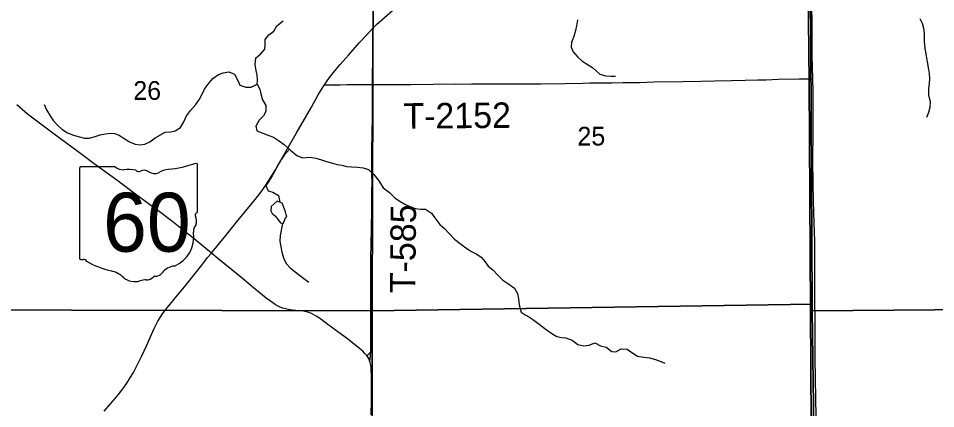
# Model space of a CAD drawing. Extents: x 1874609 to 2204689, y 815661 to 1281160.
# Drawn here: x 2036147 to 2046979, y 997204 to 1001810 of the extents above; entities that cross this region are included whole.
import ezdxf

# ---------------------------------------------------------------- set-up
doc = ezdxf.new("R2010")
doc.units = 0
for name, color, linetype in [('GM_X_County_Road', 7, 'Continuous'), ('GM_X_Minor_Lake', 7, 'Continuous'), ('GM_X_Minor_River', 7, 'Continuous'), ('GM_X_Section', 7, 'Continuous'), ('GM_X_Section_Text', 7, 'Continuous'), ('GM_X_State_Location', 7, 'Continuous'), ('GM_X_State_Route', 7, 'Continuous'), ('GM_X_State_Shield', 7, 'Continuous'), ('GM_X_Township', 7, 'Continuous'), ('GM_X_Township_Road', 7, 'Continuous'), ('GM_X_Township_Road_Text', 7, 'Continuous')]:
    doc.layers.add(name, color=color, linetype=linetype)

msp = doc.modelspace()

# ---------------------------------------------------------------- linework, layer by layer
at = {"layer": 'GM_X_County_Road'}
for points in [[(2040336, 1001697), (2040378, 1001739), (2040439, 1001794), (2040600, 1001935)], [(2039764, 1001027), (2039785, 1001059), (2039823, 1001112), (2039884, 1001190), (2039948, 1001265), (2040045, 1001376), (2040177, 1001523), (2040254, 1001608), (2040332, 1001692), (2040336, 1001697)], [(2038426, 999040), (2038435, 999050), (2038581, 999227), (2038725, 999406), (2038943, 999672), (2039014, 999762), (2039062, 999829), (2039098, 999883), (2039183, 1000023), (2039322, 1000265), (2039429, 1000450), (2039607, 1000763), (2039689, 1000906), (2039739, 1000990), (2039764, 1001027)], [(2037159, 997176), (2037235, 997262), (2037289, 997324), (2037341, 997387), (2037381, 997439), (2037427, 997506), (2037471, 997575), (2037505, 997631), (2037551, 997718), (2037601, 997821), (2037663, 997955), (2037703, 998045), (2037752, 998149), (2037796, 998237), (2037820, 998280), (2037848, 998321), (2037888, 998374), (2037992, 998500), (2038129, 998664), (2038221, 998779), (2038312, 998896), (2038382, 998987), (2038426, 999040)]]:
    msp.add_lwpolyline(points, dxfattribs=at)
at = {"layer": 'GM_X_Minor_Lake'}
for points in [[(2039262, 999630), (2039204, 999654), (2039168, 999622), (2039134, 999591), (2039127, 999539), (2039143, 999507), (2039185, 999475), (2039211, 999435), (2039241, 999396), (2039275, 999388), (2039289, 999424), (2039299, 999446), (2039317, 999470), (2039309, 999496), (2039301, 999528), (2039291, 999560)], [(2039291, 999560), (2039262, 999630)]]:
    msp.add_lwpolyline(points, dxfattribs=at)
at = {"layer": 'GM_X_Minor_River'}
for points in [[(2042751, 1001793), (2042739, 1001723), (2042725, 1001665), (2042706, 1001597), (2042680, 1001525), (2042674, 1001471), (2042697, 1001415), (2042753, 1001353), (2042803, 1001309), (2042875, 1001261), (2042929, 1001229), (2043014, 1001153), (2043086, 1001131), (2043144, 1001126), (2043198, 1001126)], [(2046791, 1001809), (2046819, 1001751), (2046835, 1001695), (2046844, 1001635), (2046842, 1001538), (2046851, 1001454), (2046869, 1001366), (2046881, 1001298), (2046894, 1001208), (2046902, 1001158), (2046908, 1001098), (2046904, 1001046), (2046893, 1000978), (2046893, 1000905), (2046913, 1000829), (2046911, 1000759), (2046896, 1000699), (2046870, 1000641)], [(2037763, 1000399), (2037880, 1000466), (2037948, 1000469), (2038000, 1000481), (2038062, 1000521), (2038100, 1000589), (2038131, 1000658), (2038179, 1000724), (2038243, 1000794), (2038285, 1000855), (2038318, 1000917), (2038344, 1000973), (2038384, 1001031), (2038442, 1001100), (2038509, 1001146), (2038565, 1001166), (2038631, 1001179), (2038700, 1001151), (2038738, 1001075), (2038762, 1001021), (2038832, 1000999), (2038898, 1000997), (2038966, 1001032), (2038972, 1001082), (2038966, 1001142), (2038957, 1001196), (2038945, 1001260), (2038951, 1001344), (2039005, 1001386), (2039056, 1001445), (2039062, 1001497), (2039060, 1001559), (2039104, 1001615), (2039164, 1001660), (2039201, 1001722), (2039275, 1001780)], [(2038966, 1001032), (2039000, 1000974), (2039011, 1000918), (2039031, 1000850), (2039069, 1000782), (2039068, 1000709), (2039042, 1000659), (2038990, 1000607), (2038950, 1000539), (2038962, 1000481), (2039033, 1000453), (2039103, 1000429), (2039159, 1000409), (2039219, 1000369), (2039287, 1000323), (2039362, 1000256), (2039436, 1000192), (2039502, 1000164), (2039590, 1000170), (2039660, 1000161), (2039726, 1000141), (2039786, 1000119), (2039857, 1000101), (2039913, 1000085), (2039965, 1000076), (2040027, 1000062), (2040081, 1000058), (2040153, 1000052), (2040217, 1000044), (2040283, 1000027), (2040343, 999969), (2040402, 999893), (2040454, 999811), (2040528, 999753), (2040591, 999693), (2040643, 999655), (2040709, 999618), (2040769, 999588), (2040835, 999564), (2040897, 999558), (2040955, 999558), (2041024, 999510), (2041064, 999457), (2041126, 999379), (2041179, 999329), (2041235, 999269), (2041299, 999203), (2041363, 999151), (2041432, 999103), (2041500, 999059), (2041560, 999028), (2041612, 998990), (2041660, 998938), (2041695, 998886), (2041749, 998842), (2041809, 998780), (2041869, 998720), (2041940, 998672), (2042006, 998627), (2042042, 998563), (2042053, 998498), (2042061, 998430), (2042083, 998344), (2042133, 998310), (2042183, 998285), (2042250, 998237), (2042378, 998137), (2042446, 998089), (2042507, 998057), (2042561, 998044), (2042611, 998040), (2042685, 998014), (2042753, 997960), (2042825, 997946), (2042887, 997955), (2042953, 997979), (2043023, 997947), (2043089, 997931), (2043154, 997877), (2043204, 997874), (2043266, 997910), (2043338, 997906), (2043392, 997866), (2043458, 997824), (2043532, 997811), (2043600, 997805), (2043672, 997785), (2043733, 997759), (2043783, 997740)], [(2036453, 1000795), (2036479, 1000731), (2036521, 1000660), (2036559, 1000604), (2036605, 1000552), (2036661, 1000504), (2036727, 1000460), (2036797, 1000432), (2036871, 1000410), (2036927, 1000394), (2036986, 1000396), (2037054, 1000416), (2037112, 1000434), (2037176, 1000448), (2037234, 1000456), (2037284, 1000452), (2037336, 1000430), (2037386, 1000399), (2037459, 1000351), (2037527, 1000327), (2037587, 1000319), (2037639, 1000325), (2037699, 1000351), (2037763, 1000399)], [(2039350, 1000267), (2039290, 1000199), (2039242, 1000131), (2039200, 1000059), (2039175, 1000006), (2039143, 999952), (2039103, 999888), (2039071, 999836), (2039098, 999776), (2039152, 999758), (2039220, 999718), (2039236, 999641)], [(2039266, 999390), (2039240, 999249), (2039236, 999181), (2039246, 999113), (2039259, 999049), (2039277, 998983), (2039311, 998917), (2039362, 998863), (2039416, 998817), (2039502, 998753), (2039576, 998697)]]:
    msp.add_lwpolyline(points, dxfattribs=at)
at = {"layer": 'GM_X_Section'}
for points in [[(2045495, 1003744), (2045493, 1003680), (2045523, 998437), (2040326, 998360), (2040341, 1003676)], [(2040341, 1003676), (2040326, 998360), (2034995, 998370), (2035032, 1003676)], [(2045493, 1003680), (2050756, 1003688), (2050820, 998403), (2045523, 998359), (2045523, 998437)], [(2040326, 998360), (2045523, 998437), (2045523, 998359), (2045597, 993088), (2040325, 993064)], [(2034995, 998370), (2040326, 998360), (2040325, 993064), (2035022, 993074)], [(2045523, 998359), (2050820, 998403), (2050862, 993115), (2050738, 993114), (2045597, 993088)]]:
    msp.add_lwpolyline(points, close=True, dxfattribs=at)
at = {"layer": 'GM_X_State_Route'}
msp.add_lwpolyline([(2040314, 997130), (2040316, 997293), (2040317, 997457), (2040317, 997605), (2040315, 997654), (2040313, 997686), (2040308, 997719), (2040301, 997750), (2040298, 997759), (2040290, 997781), (2040284, 997795), (2040276, 997809), (2040261, 997830), (2040257, 997835), (2040236, 997860), (2040213, 997883), (2040176, 997915), (2040034, 998026), (2039876, 998143), (2039772, 998222), (2039705, 998270), (2039664, 998297), (2039636, 998313), (2039607, 998326), (2039576, 998337), (2039545, 998346), (2039513, 998353), (2039465, 998359), (2039383, 998367), (2039334, 998375), (2039302, 998382), (2039270, 998391), (2039239, 998403), (2039209, 998418), (2039180, 998434), (2039125, 998471), (2039072, 998509), (2038945, 998613), (2038793, 998738), (2038666, 998842), (2038502, 998977), (2038426, 999040), (2038338, 999113), (2038223, 999206), (2038134, 999278), (2037954, 999420), (2037810, 999530), (2037652, 999646), (2037518, 999742), (2037309, 999900), (2037044, 1000094), (2036913, 1000192), (2036780, 1000288), (2036569, 1000445), (2036332, 1000621), (2036255, 1000681), (2036192, 1000734), (2036131, 1000790)], dxfattribs=at)
at = {"layer": 'GM_X_State_Shield'}
for p, q in [((2037292, 1000056), (2036884, 1000056)), ((2038263, 999529), (2038263, 1000082)), ((2036871, 1000038), (2036871, 998981)), ((2038263, 999530), (2038263, 999529))]:
    msp.add_line(p, q, dxfattribs=at)
for centre, radius, start, end in [((2036886, 1000040), 16.1, 98.1301, 188.1301), ((2037389, 1000179), 156, 231.6195, 271.1119), ((2037767, 1001497), 1476, 275.8445, 288.9065), ((2038247, 1000084), 15.5, 351.8621, 97.738), ((2037441, 999463), 562, 80.4867, 94.9883), ((2037568, 1000046), 45.1, 219.7921, 297.1024), ((2037635, 999923), 93.8, 54.4667, 119.1411), ((2037756, 1000091), 113, 233.8562, 294.8282), ((2037955, 999733), 297, 97.3462, 120.7689), ((2038259, 999489), 24, 107.944, 210.337), ((2038246, 999527), 16.6, 289.6038, 7.7341), ((2038107, 999419), 144, 340.033, 23.6496), ((2038318, 999298), 105, 136.8065, 186.9296), ((2037849, 999228), 369, 292.3089, 8.9858), ((2036887, 998979), 16.3, 171.9584, 258.3066), ((2036889, 999087), 124, 267.339, 280.6039), ((2036915, 998920), 44.8, 29.7484, 93.2717), ((2037480, 999870), 1066, 240.4129, 257.1985), ((2038005, 998685), 202, 94.4031, 142.5768), ((2037162, 998506), 334, 47.1842, 75.836), ((2037523, 998915), 212, 230.7004, 286.2918), ((2037660, 998836), 113, 268.777, 315.5493), ((2037762, 998734), 31.8, 65.7517, 132.6484), ((2037749, 998879), 119, 282.8732, 323.2771), ((2037645, 998550), 174, 85.6951, 111.2099)]:
    msp.add_arc(centre, radius, start, end, dxfattribs=at)
at = {"layer": 'GM_X_Township'}
for points in [[(2045517, 995688), (2045485, 1001053), (2045459, 1003657), (2045459, 1004485), (2045458, 1009548), (2045436, 1012970), (2045427, 1014495), (2045393, 1019676), (2045376, 1022315), (2045360, 1024926), (2052051, 1024960), (2055039, 1024975), (2058377, 1024992), (2063573, 1025019), (2069086, 1025067), (2071562, 1025082), (2071697, 1021700), (2071830, 1014457), (2071852, 1012905), (2071861, 1011952), (2071887, 1008769), (2071889, 1006520), (2071959, 1001676), (2072021, 996047)], [(2030478, 1025070), (2037504, 1025002), (2040549, 1024973), (2043822, 1024941), (2045360, 1024926), (2045376, 1022315), (2045393, 1019676), (2045427, 1014495), (2045436, 1012970), (2045458, 1009548), (2045459, 1004485), (2045459, 1003657), (2045485, 1001053), (2045517, 995688)]]:
    msp.add_lwpolyline(points, dxfattribs=at)
at = {"layer": 'GM_X_Township_Road'}
for points in [[(2040336, 1001697), (2040337, 1001716), (2040338, 1001863), (2040338, 1001994), (2040337, 1002191), (2040338, 1002667), (2040337, 1002913), (2040336, 1003193), (2040337, 1003258), (2040341, 1003308), (2040348, 1003357), (2040360, 1003405), (2040375, 1003452), (2040449, 1003653), (2040463, 1003687)], [(2045528, 1001098), (2045528, 1001100), (2045523, 1001362), (2045520, 1001542), (2045520, 1001755), (2045517, 1001952), (2045510, 1002378), (2045509, 1002542), (2045506, 1002722), (2045503, 1002902), (2045500, 1003082), (2045498, 1003230), (2045501, 1003377), (2045503, 1003476), (2045502, 1003541), (2045500, 1003592), (2045500, 1003676)], [(2040330, 1001029), (2040329, 1001076), (2040330, 1001158), (2040333, 1001289), (2040334, 1001404), (2040335, 1001617), (2040336, 1001697)], [(2039764, 1001027), (2039800, 1001027), (2039881, 1001026), (2039947, 1001027), (2040029, 1001028), (2040160, 1001029), (2040330, 1001029)], [(2040308, 997871), (2040310, 997946), (2040311, 998028), (2040310, 998208), (2040311, 998422), (2040311, 998668), (2040311, 998882), (2040311, 999029), (2040312, 999095), (2040313, 999160), (2040318, 999307), (2040323, 999570), (2040323, 999696), (2040322, 999778), (2040324, 999863), (2040322, 999978), (2040322, 1000126), (2040323, 1000208), (2040323, 1000273), (2040326, 1000436), (2040327, 1000502), (2040328, 1000584), (2040331, 1000715), (2040331, 1000912), (2040330, 1001011), (2040330, 1001029)], [(2040330, 1001029), (2040422, 1001029), (2040701, 1001029), (2040783, 1001030), (2041044, 1001035), (2041159, 1001036), (2041307, 1001035), (2041503, 1001036), (2041700, 1001036), (2041847, 1001037), (2041929, 1001038), (2042109, 1001039), (2042214, 1001039)], [(2042214, 1001039), (2042322, 1001039), (2042601, 1001042), (2042814, 1001046), (2042896, 1001048), (2043043, 1001050), (2043158, 1001050), (2043289, 1001052), (2043486, 1001054), (2043650, 1001059), (2043994, 1001066), (2044207, 1001070), (2044370, 1001074), (2044567, 1001077), (2044731, 1001081), (2044878, 1001084), (2044976, 1001086), (2045124, 1001091), (2045369, 1001095), (2045484, 1001097), (2045528, 1001098)], [(2045536, 999698), (2045534, 999805), (2045532, 999919), (2045529, 1000067), (2045528, 1000215), (2045531, 1000395), (2045534, 1000559), (2045534, 1000690), (2045531, 1000952), (2045528, 1001098)], [(2045568, 997088), (2045563, 997350), (2045561, 997531), (2045558, 997826), (2045555, 998186), (2045551, 998531), (2045551, 998629), (2045553, 998793), (2045553, 998875), (2045551, 998924), (2045551, 998987), (2045553, 999036), (2045553, 999102), (2045551, 999200), (2045549, 999265), (2045548, 999314), (2045546, 999379), (2045540, 999543), (2045537, 999625), (2045536, 999698)], [(2040261, 997830), (2040267, 997835), (2040278, 997845), (2040285, 997851), (2040290, 997855), (2040303, 997867), (2040308, 997871)], [(2040298, 997759), (2040301, 997787), (2040303, 997803), (2040305, 997814), (2040306, 997827), (2040307, 997848), (2040308, 997871)]]:
    msp.add_lwpolyline(points, dxfattribs=at)

# ---------------------------------------------------------------- texts
at = {"layer": 'GM_X_Section_Text'}
for s, p in [('26', (2037504, 1000848)), ('25', (2042749, 1000309))]:
    msp.add_text(s, height=221, rotation=0, dxfattribs=at).set_placement(p)
at = {"layer": 'GM_X_State_Location'}
for s in ['s', 'r']:
    msp.add_text(s, height=1, dxfattribs=at).set_placement((2037551, 999439))
msp.add_text('60', height=1, rotation=0, dxfattribs=at).set_placement((2037299, 999367))
at = {"layer": 'GM_X_State_Shield'}
msp.add_text('60', height=696.1, dxfattribs=at).set_placement((2037147, 999056))
at = {"layer": 'GM_X_Township_Road_Text'}
for s, rotation, p in [('T-2152', 0.4556, (2040694, 1000508)), ('T-585', 89.4517, (2040834, 998565))]:
    msp.add_text(s, height=300, rotation=rotation, dxfattribs=at).set_placement(p)

doc.saveas('drawing.dxf')
